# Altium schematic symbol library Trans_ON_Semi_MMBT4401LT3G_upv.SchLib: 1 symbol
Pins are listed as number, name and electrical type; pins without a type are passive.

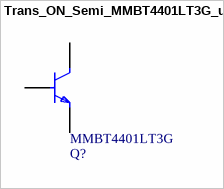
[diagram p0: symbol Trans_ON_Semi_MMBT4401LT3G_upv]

## Trans_ON_Semi_MMBT4401LT3G_upv
designator Q?  Part Number: MMBT4401LT3G
TRANS Bipolar (BJT) Transistor NPN 40V 600mA 250MHz 300mW Surface Mount SOT-23-3 (TO-236); Manufacturer: ON Semi
footprint ON_Semi_CASE_318-08_ISSUE_AR_0
pins: 1 BASE, 2 EMITTER, 3 COLLECTOR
